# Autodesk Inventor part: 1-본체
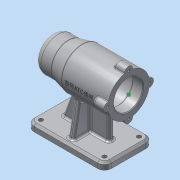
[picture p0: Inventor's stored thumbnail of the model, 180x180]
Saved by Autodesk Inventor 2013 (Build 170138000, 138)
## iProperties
Created: 2019-07
Part Number: 1-본체
Material: 알루미늄 6061
Document SubType Name: Modeling
Designer: Administrator
Density: 2.71 g/cm^3
Mass: 646.774 g
Surface Area: 654.083 cm^2
Volume: 238.662 cm^3
Author: Administrator
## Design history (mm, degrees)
sketch "스케치1"
  geometry: L1 (0, 0)-(-112, 0); L2 (0, 0)-(0, 30); L3 (0, 30)-(-67, 30); L4 (-67, 30)-(-87, 25); L5 (-87, 25)-(-112, 25); L6 (-112, 25)-(-112, 0)
  constraints: 12 end point, 3 perpendicular, 1 horizontal, 1 parallel
  dimensions: "d0" = 112 distance of L1.start L1.end; "d1" = 60 diameter of L3 L1; "d2" = 50 diameter of L5 L1; "d3" = 25 distance of L4.end L5.end; "d4" = 45 distance from line of L3.end L6
revolve "회전1" sketch "스케치1" stored, may be unused: angle "d5" = 90 deg
sketch "스케치3"
  geometry: C1 r 30 at (0, 0) reference; C2 r 21 at (0, 0)
  constraints: 1 centre point, 1 coincident
  dimensions: "d7" = 42 diameter of C2
extrude "돌출1" cut sketch "스케치3" distance "d9" = 15; taper "d10" = 0 deg
sketch "스케치4"
  geometry: C1 r 21 at (0, 0) reference; C2 r 24 at (0, 0)
  constraints: 1 centre point, 1 coincident
  dimensions: "d11" = 48 diameter of C2
extrude "돌출2" cut sketch "스케치4" distance "d13" = 54; taper "d14" = 0 deg
sketch "스케치5"
  geometry: C1 r 24 at (0, 0) reference; C2 r 21 at (0, 0)
  constraints: 1 centre point, 1 coincident
  dimensions: "d15" = 42 diameter of C2
extrude "돌출3" cut sketch "스케치5" distance "d17" = 12; taper "d18" = 0 deg
sketch "스케치6"
  geometry: C1 r 21 at (0, 0) reference; C2 r 17.5 at (0, 0)
  constraints: 1 centre point, 1 coincident
  dimensions: "d19" = 35 diameter of C2
extrude "돌출4" cut sketch "스케치6" distance "d21" = 18; taper "d22" = 0 deg
sketch "스케치7"
  geometry: C1 r 17.5 at (0, 0) reference; C2 r 16 at (0, 0)
  constraints: 1 centre point, 1 coincident
  dimensions: "d23" = 32 diameter of C2
extrude "돌출5" cut sketch "스케치7" distance "d25" = 4; taper "d26" = 0 deg
sketch "스케치8"
  geometry: C1 r 16 at (0, 0) reference; C2 r 10.5 at (0, 0)
  constraints: 1 centre point, 1 coincident
  dimensions: "d27" = 21 diameter of C2
extrude "돌출6" cut sketch "스케치8" distance "d29" = 3; taper "d30" = 0 deg
sketch "스케치9"
  geometry: 1 further point
node "작업 평면1"
sketch "스케치10"
  geometry: L1 (0, 35)-(112, 35); L2 (112, 35)-(112, -35); L3 (112, -35)-(0, -35); L4 (0, -35)-(0, 35); 2 further points
  constraints: 8 end point, 2 parallel, 1 coincident, 1 horizontal, 1 midpoint, 1 perpendicular
  dimensions: "d32" = 112 distance of L1.start L1.end; "d34" = 70 distance of L1.end L2.end
extrude "돌출7" join sketch "스케치10" distance "d35" = 10; taper "d36" = 0 deg
node "작업 평면2"
sketch "스케치11"
  geometry: L1 (-10, 70)-(-10, 0) reference; L2 (0, 0)-(-10, 0) reference; L3 (0, 70)-(-10, 70) reference; L4 (-10, 7)-(-57.334, 15.346); L5 (-57.334, 54.654)-(-10, 63); A1 r 30 centre (-80, 35) between (-57.334, 15.346) and (-57.334, 54.654) reference; 1 further point
  constraints: 4 end point, 2 point on circle, 2 point on line, 1 equal length
  dimensions: "d37" = 7 distance of L4.start L1.end; "d38" = 100 deg angle of L4 L1; "d39" = 7 distance of L5.end L1.start
extrude "돌출8" join sketch "스케치11" stored distance "d40" = 8; taper "d41" = 0 deg
sketch "스케치12"
  geometry: L1 (87, -25)-(67, -30) reference; L2 (112, -25)-(87, -25) reference; L3 (67, -30)-(0, -30) reference; L4 (60, -22.666)-(60, -70) reference; L5 (0, -70)-(112, -70) reference; L6 (112, -80)-(112, -70) reference; L7 (92, -70)-(76.57, -27.607); 1 further point
  constraints: 2 end point, 2 point on line
  dimensions: "d42" = 20 distance of L7.start L5.end; "d43" = 110 deg angle of L7 L5
feature "리브1" sketch "스케치12" dims "d44" = 1, "d45" = 8, "d46" = 0, "d47" = 0, "d48" = 1, "d49" = 1
sketch "스케치13"
  geometry: L1 (52, -30)-(0, -30) reference; L2 (52, -70)-(52, -22.666) reference; L3 (0, -70)-(112, -70) reference; L4 (25, -70)-(25, -30); 1 further point
  constraints: 2 end point, 2 point on line, 1 perpendicular
  dimensions: "d50" = 25 distance of L3.start L4.start
feature "리브2" sketch "스케치13" dims "d51" = 1, "d52" = 8, "d53" = 0, "d54" = 0, "d55" = 1, "d56" = 1
sketch "스케치14"
  geometry: L1 (-112, 35)-(-112, -35) reference; L2 (-112, -35)-(0, -35) reference; L3 (0, 35)-(-112, 35) reference; L4 (0, 0)-(-112, 0); L5 (-56, 35)-(-56, -35); C1 r 3 at (-102, 25)
  constraints: 4 end point, 3 midpoint, 1 centre point
  dimensions: "d57" = 6 diameter of C1; "d59" = 25 distance from line of L4 C1.centre; "d60" = 46 distance from line of L5 C1.centre
extrude "돌출9" cut sketch "스케치14" stored distance "d61" = 8; taper "d62" = 0 deg
sketch "스케치15"
  geometry: A1 r 30 centre (0, 0) between (-30, 0) and (-29.4, -5.97) reference; A2 r 6 centre (-30, 0) between (-29.4, 5.97) and (-29.4, -5.97)
  constraints: 5 point on circle, 1 centre point, 1 horizontal alignment
  dimensions: "d69" = 12 diameter of A2
extrude "돌출10" join sketch "스케치15" distance "d71" = 16; taper "d72" = 0 deg
sketch "스케치16"
  geometry: A1 r 6 centre (0, 0) between (0.6, 5.97) and (0.6, -5.97) reference; 1 further point
  constraints: 1 coincident
hole "구멍1" sketch "스케치16" at (0, 0) diameter "d76" = 3.242; stored, may be unused: countersink angle "d80" = 90 deg, drill point angle "d82" = 118 deg; dims "d77" = 8, "d78" = 4, "d79" = 2, "d81" = 11
node "작업 평면3"
sketch "스케치17"
  geometry: 2 further points
  constraints: 1 horizontal alignment, 1 other
  dimensions: "d87" = 42 distance of point (-42, 0) point (0, 0)
feature "엠보싱1" sketch "스케치17" dims "d88" = 0.5, "d89" = 0
fillet "모깎기1" dims "d90" = 10
fillet "모깎기2" dims "d91" = 10
fillet "모깎기14" dims "d103" = 3
fillet "모깎기15" dims "d104" = 3
fillet "모깎기16" dims "d105" = 3
chamfer "모따기1" distance "d106" = 3; stored, may be unused: second distance "d107" = 2, angle "d108" = 45 deg
chamfer "모따기2" distance "d109" = 1; stored, may be unused: second distance "d110" = 2, angle "d111" = 45 deg
fillet "모깎기17" dims "d112" = 3
fillet "모깎기20" dims "d115" = 0.3
fillet "모깎기23" dims "d118" = 0.3
fillet "모깎기24" dims "d119" = 0.3
fillet "모깎기25" dims "d120" = 3
fillet "모깎기26" dims "d121" = 3
fillet "모깎기27" dims "d122" = 3
fillet "모깎기28" dims "d123" = 1
node "솔리드1"
pattern_linear "직사각형 패턴1" dims "d65" = 92
pattern_circular "원형 패턴1" dims angle "d74" = 360 deg
pattern_circular "원형 패턴2" dims angle "d84" = 360 deg
